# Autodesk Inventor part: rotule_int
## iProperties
Author: robert
Shininess: 25.0
PropertySet Name: _Private Model Information
Compacted: True
Length Units: 11269
Angle Units: 11283
Time Units: 11279
Mass Units: 11290
Length Display Precision: 3
Angle Display Precision: 2
Created: 2001-08
Part Number: rotule_int
Material: Bronze (étain doux)
Document SubType Name: Modélisation
Designer: robert
Control State: 0
Master: False
Checked Out: False
PropertySet Name: Design Tracking Control
Density: 8.874
Volumn: 3.6798521949048433
Area: 20.794169151616245
PropertySet Name: Model Information
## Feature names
1. Révolution1 [Revolution]
